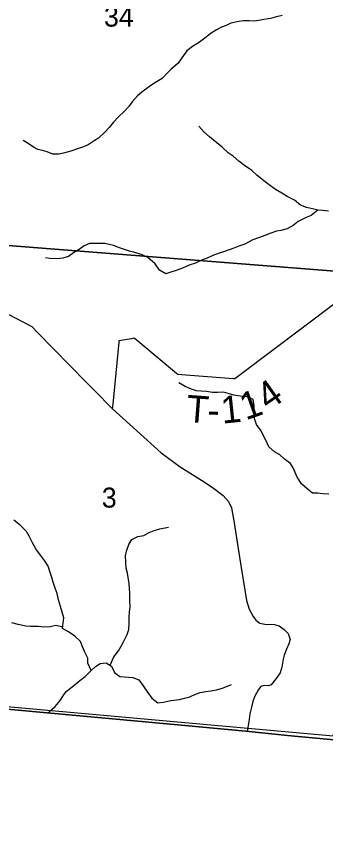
# Model space of a CAD drawing. Extents: x 1715311 to 2083412, y 146837 to 553079.
# Drawn here: x 1966796 to 1970212, y 307641 to 316815 of the extents above; entities that cross this region are included whole.
import ezdxf

# ---------------------------------------------------------------- set-up
doc = ezdxf.new("R2010")
doc.units = 0
for name, color, linetype in [('GM_X_Adjacent_County', 7, 'Continuous'), ('GM_X_County', 7, 'Continuous'), ('GM_X_Minor_River', 7, 'Continuous'), ('GM_X_Section', 7, 'Continuous'), ('GM_X_Section_Text', 7, 'Continuous'), ('GM_X_Township', 7, 'Continuous'), ('GM_X_Township_Road', 7, 'Continuous'), ('GM_X_Township_Road_Text', 7, 'Continuous'), ('GM_X_Township_ROW', 7, 'Continuous')]:
    doc.layers.add(name, color=color, linetype=linetype)

msp = doc.modelspace()

# ---------------------------------------------------------------- linework, layer by layer
at = {"layer": 'GM_X_Adjacent_County'}
msp.add_lwpolyline([(1962033.5, 309585.4), (1968500, 308993.3), (1969333.1, 308914.5), (1969792.9, 308867.9), (1973036.6, 308563.8), (1974921.4, 308385.3), (1978099, 308006.1), (1980094.8, 307768), (1981158.3, 307641.1), (1981333.8, 309559.5), (1981413.6, 310431.3), (1981491.3, 311279.7), (1981647.4, 312985.2), (1981968.5, 316493.7), (1982170.3, 318699.4), (1982895.7, 327173.9), (1982963.5, 327965.4), (1983031.4, 328758.3), (1983804.4, 337791.6), (1984006.9, 340156)], dxfattribs=at)
at = {"layer": 'GM_X_County'}
msp.add_lwpolyline([(1984006.9, 340156), (1983804.4, 337791.6), (1983031.4, 328758.3), (1982963.5, 327965.4), (1982895.7, 327173.9), (1982170.3, 318699.4), (1981968.5, 316493.7), (1981647.4, 312985.2), (1981491.3, 311279.7), (1981413.6, 310431.3), (1981333.8, 309559.5), (1981158.3, 307641.1), (1980094.8, 307768), (1978099, 308006.1), (1974921.4, 308385.3), (1973036.6, 308563.8), (1969792.9, 308867.9), (1969333.1, 308914.5), (1968500, 308993.3), (1962033.5, 309585.4)], dxfattribs=at)
at = {"layer": 'GM_X_Minor_River'}
for points in [[(1969734.1, 316827.5), (1969656, 316807.4), (1969606, 316793.4), (1969529.9, 316781.3), (1969475.8, 316771.3), (1969423.8, 316763.3), (1969367.7, 316767.3), (1969301.6, 316767.2), (1969237.5, 316757.2), (1969167.5, 316743.1), (1969115.4, 316715.1), (1969063.3, 316697), (1969009.3, 316669), (1968949.2, 316632.9), (1968879.1, 316576.8), (1968821, 316530.7), (1968740.9, 316484.5), (1968678.8, 316434.4), (1968622.7, 316360.3), (1968584.7, 316298.2), (1968503.9, 316229.6)], [(1968503.9, 316229.6), (1968461, 316189.5), (1968405, 316129.4), (1968333, 316087.3), (1968281, 316053.2), (1968182.9, 315979), (1968132.9, 315936.9), (1968072.9, 315870.7), (1968036.9, 315820.6), (1967990.9, 315768.5), (1967920.9, 315702.3), (1967866.9, 315648.2), (1967818.9, 315590), (1967774.9, 315539.9), (1967702.8, 315471.8), (1967652.8, 315441.7), (1967586.8, 315397.5), (1967536.7, 315375.5), (1967458.7, 315347.4), (1967396.7, 315325.3), (1967314.6, 315305.2), (1967262.6, 315293.2), (1967196.5, 315295.1), (1967134.4, 315321.1), (1967082.4, 315333.1), (1967032.3, 315345.1), (1966982.3, 315371.1), (1966924.2, 315413.1), (1966870.2, 315443.2)], [(1970248.2, 314662.2), (1970180.1, 314670.2), (1970128, 314676.1), (1970070, 314688.1), (1970001.9, 314704.1), (1969935.8, 314730.2), (1969871.8, 314786.2), (1969787.7, 314824.3), (1969731.6, 314862.3), (1969661.6, 314904.3), (1969589.5, 314954.4), (1969529.4, 315000.4), (1969453.4, 315062.5), (1969397.3, 315112.6), (1969317.2, 315168.6), (1969253.2, 315216.7), (1969193.1, 315270.8), (1969135.1, 315308.8), (1969069, 315370.8), (1969010.9, 315418.9), (1968930.9, 315485), (1968868.8, 315539), (1968810.8, 315605.1)], [(1970127, 314676.4), (1970053.9, 314616), (1969999.9, 314594), (1969911.8, 314549.9), (1969855.7, 314503.8), (1969789.6, 314467.7), (1969719.5, 314451.6), (1969669.5, 314441.6), (1969609.4, 314421.5), (1969541.3, 314393.5), (1969473.2, 314369.4), (1969411.1, 314345.3), (1969321, 314299.2), (1969252.9, 314275.1), (1969198.9, 314253.1), (1969148.8, 314235), (1969096.8, 314219), (1969036.7, 314200.9), (1968968.6, 314172.9), (1968902.5, 314144.8), (1968834.4, 314118.7), (1968774.4, 314090.6), (1968706.3, 314066.6), (1968630.2, 314034.5), (1968560.1, 314006.4), (1968503.9, 313987.6)], [(1968503.9, 313987.6), (1968446.3, 313971.6), (1968378.2, 314009.6), (1968328.1, 314079.7), (1968248, 314151.8), (1968184, 314179.8), (1968105.9, 314205.8), (1968045.8, 314221.8), (1967989.8, 314239.8), (1967935.7, 314257.8), (1967867.6, 314283.8), (1967773.5, 314305.7), (1967713.5, 314307.7), (1967661.5, 314307.7), (1967601.4, 314305.6), (1967545.4, 314279.5), (1967487.3, 314239.4), (1967425.3, 314201.3), (1967371.3, 314161.2), (1967309.3, 314145.1), (1967241.2, 314137.1), (1967165.1, 314141), (1967115.1, 314147)], [(1970249.4, 311535.1), (1970183.3, 311539.1), (1970129.3, 311545), (1970071.2, 311547), (1970007.1, 311599.1), (1969949.1, 311649.1), (1969899, 311723.2), (1969877, 311773.3), (1969855, 311825.4), (1969827, 311875.5), (1969760.9, 311921.5), (1969708.9, 311969.6), (1969648.8, 312003.6), (1969584.8, 312059.7), (1969558.7, 312125.8), (1969528.7, 312181.8), (1969500.7, 312233.9), (1969450.7, 312304), (1969426.7, 312372.1), (1969418.7, 312450.2), (1969424.7, 312512.3), (1969412.7, 312580.5), (1969348.6, 312610.5), (1969268.5, 312618.5), (1969200.5, 312628.4), (1969136.4, 312646.5), (1969086.3, 312662.5), (1969018.3, 312660.4), (1968962.2, 312658.4), (1968896.1, 312668.4), (1968836.1, 312672.4), (1968782, 312678.4), (1968711.9, 312702.4), (1968659.9, 312726.4), (1968591.8, 312764.4)], [(1967619.6, 309586.7), (1967586, 309667.3), (1967584, 309721.4), (1967549.9, 309789.5), (1967529.9, 309841.6), (1967501.8, 309907.7), (1967439.7, 309965.8), (1967371.6, 310011.8), (1967305.6, 310051.8), (1967311.5, 310108), (1967317.5, 310168.1), (1967301.5, 310232.2), (1967281.4, 310294.3), (1967261.3, 310368.4), (1967245.3, 310436.5), (1967221.2, 310494.6), (1967201.2, 310562.7), (1967187.1, 310614.8), (1967169.1, 310668.9), (1967145, 310739), (1967105, 310803), (1967060.9, 310861.1), (1967008.8, 310929.2), (1966972.7, 310995.3), (1966936.7, 311069.4), (1966904.6, 311121.5), (1966836.5, 311191.6), (1966764.4, 311247.6)], [(1967830, 309643.2), (1967872.2, 309735.7), (1967924.2, 309803.8), (1967954.2, 309853.9), (1967980.2, 309904), (1968020.2, 309982.2), (1968038.2, 310038.3), (1968042.1, 310110.4), (1968042.1, 310174.5), (1968046.1, 310232.7), (1968052, 310284.8), (1968048, 310360.9), (1968047.9, 310439), (1968045.9, 310493.1), (1968041.9, 310547.2), (1968029.8, 310613.3), (1968023.8, 310663.4), (1968009.8, 310717.5), (1968003.7, 310781.6), (1968001.7, 310851.7), (1968011.7, 310905.8), (1968037.6, 310980), (1968069.6, 311032.1), (1968135.7, 311066.2), (1968203.7, 311078.3), (1968263.8, 311110.4), (1968317.8, 311134.4), (1968379.8, 311152.5), (1968476.7, 311172)], [(1967306.8, 310063.2), (1967229.5, 310083.8), (1967169.4, 310069.8), (1967097.4, 310063.7), (1967037.3, 310071.7), (1966951.3, 310071.6), (1966897.2, 310077.6), (1966813.1, 310095.6), (1966745.1, 310113.6)], [(1967144.9, 309118.4), (1967164, 309136.1), (1967224, 309188.3), (1967278, 309252.4), (1967312, 309304.5), (1967344, 309354.6), (1967428, 309418.8), (1967494, 309475), (1967556.1, 309519.1), (1967620.1, 309587.2), (1967670.1, 309631.3), (1967722.1, 309663.4), (1967786.2, 309669.5), (1967846.2, 309633.5), (1967878.3, 309563.4), (1967938.4, 309519.3), (1968082.5, 309507.4), (1968146.6, 309483.4), (1968194.7, 309415.3), (1968244.7, 309347.2), (1968292.8, 309279.1), (1968358.9, 309227.1), (1968422.9, 309235.1), (1968504, 309252.3)], [(1968504, 309252.3), (1968597, 309264.7), (1968655, 309280.8), (1968713.1, 309294.8), (1968775.2, 309322.9), (1968827.2, 309343), (1968889.3, 309355), (1968943.4, 309361), (1969007.4, 309373.1), (1969073.5, 309391.1), (1969173.6, 309431.2)]]:
    msp.add_lwpolyline(points, dxfattribs=at)
at = {"layer": 'GM_X_Section'}
for points in [[(1965361.2, 319827.2), (1971001.4, 319276), (1970504.2, 313985.5), (1965290.6, 314392.9), (1964870.5, 314425.2)], [(1965290.6, 314392.9), (1970504.2, 313985.5), (1970768.2, 313957.7), (1970297.6, 308860.5), (1964968.2, 309337.4)]]:
    msp.add_lwpolyline(points, close=True, dxfattribs=at)
at = {"layer": 'GM_X_Township'}
msp.add_lwpolyline([(1984006.9, 340156), (1983804.4, 337791.6), (1983031.4, 328758.3), (1982963.5, 327965.4), (1982895.7, 327173.9), (1982170.3, 318699.4), (1981968.5, 316493.7), (1981647.4, 312985.2), (1981491.3, 311279.7), (1981413.6, 310431.3), (1981333.8, 309559.5), (1981158.3, 307641.1), (1980094.8, 307768), (1978099, 308006.1), (1974921.4, 308385.3), (1973036.6, 308563.8), (1969792.9, 308867.9), (1969333.1, 308914.5), (1968500, 308993.3), (1962033.5, 309585.4)], dxfattribs=at)
at = {"layer": 'GM_X_Township_Road'}
for points in [[(1965917.9, 314418.5), (1965942.6, 314380.1), (1966213.9, 313958.4), (1966226.5, 313938.6), (1966272.3, 313888.7), (1966518.8, 313619.8), (1966521.1, 313617.3), (1966599.1, 313577), (1966963.7, 313388.6), (1966964, 313388.4), (1967027.5, 313323.6), (1967569.9, 312770), (1967719.6, 312617.2)], [(1967857.9, 312477.6), (1967863, 312530.4), (1967930.2, 313216.3), (1967931.9, 313233.8), (1968019.1, 313248.5), (1968071.4, 313257.3), (1968098.2, 313261.8), (1968158.9, 313211.5), (1968566.7, 312872.7), (1968579.2, 312862.2), (1968668.6, 312855.4), (1969197.2, 312815), (1969208.5, 312814), (1969284.2, 312870.9), (1970641.3, 313889.1), (1970677.4, 313916.3), (1970737.8, 313911.9), (1971901.1, 313827.8), (1971953.9, 313823.9)], [(1967719.6, 312617.2), (1967793.3, 312542), (1967809.7, 312524.9), (1967857.9, 312477.6), (1968397.2, 311992.4), (1968604.1, 311838.7), (1968870.1, 311671.7), (1968973.5, 311602.3), (1969081.4, 311519.5), (1969142, 311453), (1969174.5, 311385.1), (1969201.4, 311219.2)]]:
    msp.add_lwpolyline(points, dxfattribs=at)
at = {"layer": 'GM_X_Township_ROW'}
msp.add_lwpolyline([(1969201.4, 311219.2), (1969263.1, 310838.3), (1969338.7, 310360.6), (1969368.5, 310262.5), (1969413.1, 310182.2), (1969442.8, 310140.6), (1969487.4, 310107.9), (1969540.9, 310099), (1969647.9, 310096), (1969701.4, 310081.1), (1969754.9, 310039.5), (1969799.5, 309994.9), (1969823.3, 309929.5), (1969808.4, 309879), (1969781.7, 309822.5), (1969754.9, 309754.1), (1969746, 309709.6), (1969731.1, 309623.4), (1969710.3, 309560.9), (1969665.7, 309495.5), (1969612.2, 309427.2), (1969582.5, 309415.3), (1969534.9, 309418.2), (1969499.3, 309409.3), (1969472.5, 309376.6), (1969427.9, 309293.4), (1969410.1, 309242.9), (1969395.2, 309180.4), (1969377.4, 309106.1), (1969365.5, 309019.9), (1969346.5, 308913.3)], dxfattribs=at)

# ---------------------------------------------------------------- texts
at = {"layer": 'GM_X_Section_Text'}
for s, p in [('34', (1967763.2, 316703.9)), ('3', (1967739, 311386.5))]:
    msp.add_text(s, height=221, rotation=0.00001, dxfattribs=at).set_placement(p)
at = {"layer": 'GM_X_Township_Road_Text'}
for s, rotation, p in [('4', 35.11684, (1969584, 312452)), ('1', 19.39738, (1969330.2, 312349.6)), ('T', 355.68446, (1968666.3, 312334.4)), ('1', 5.93625, (1969071.6, 312313.7)), ('-', 357.8306, (1968902.3, 312316.9))]:
    msp.add_text(s, height=300, rotation=rotation, dxfattribs=at).set_placement(p)

doc.saveas('drawing.dxf')
